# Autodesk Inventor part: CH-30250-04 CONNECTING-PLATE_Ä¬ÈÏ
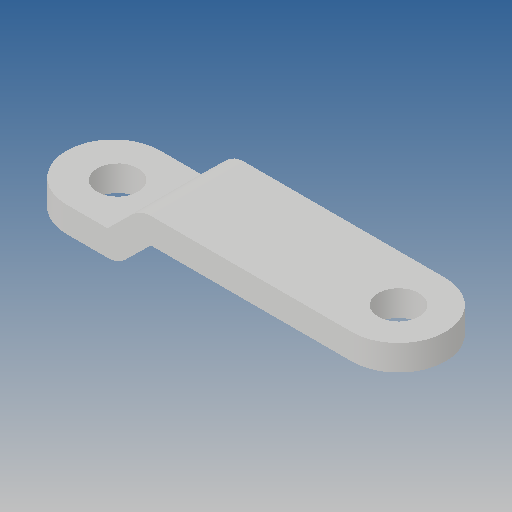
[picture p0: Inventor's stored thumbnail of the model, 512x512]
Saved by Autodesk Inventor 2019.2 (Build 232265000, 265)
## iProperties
Created: 2010-06
Part Number: CH-30250-04 CONNECTING-PLATE_Ä¬ÈÏ
Material: Ogólny
Document SubType Name: Modeling
Designer: CADENGINEERING4
Density: 1 g/cm^3
Appearance: Domyślna
Author: CADENGINEERING4
Revision Number: ÈÎºÎ
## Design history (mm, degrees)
feature "NONE"
node "Bryła1"
